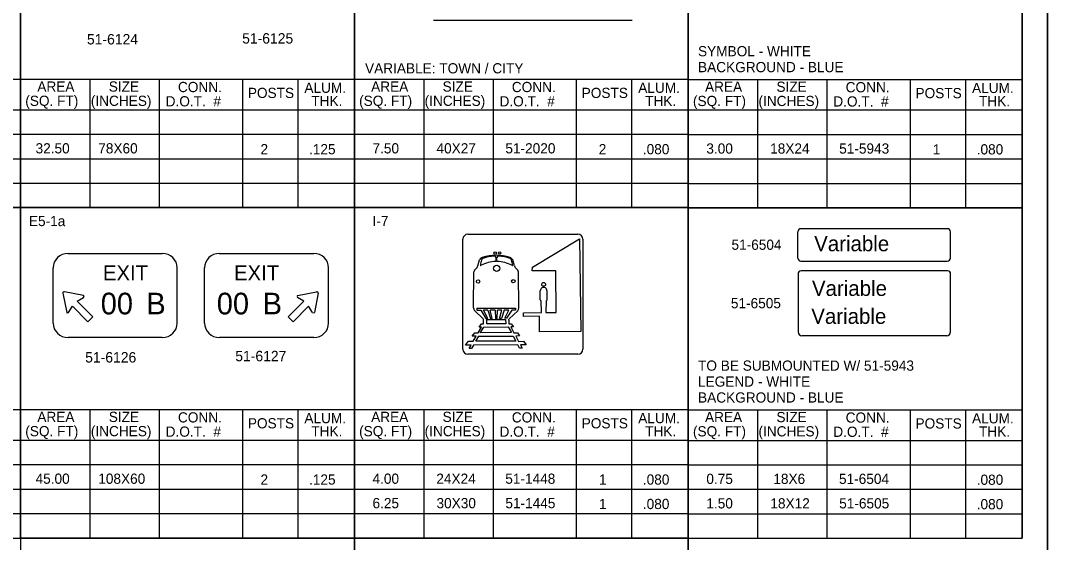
# Model space of a CAD drawing. Extents: x 0 to 2011, y -22 to 1183.
# Drawn here: x 947.8 to 1270, y 495.4 to 659.1 of the extents above; entities that cross this region are included whole.
import ezdxf

# ---------------------------------------------------------------- set-up
doc = ezdxf.new("R2010")
doc.units = 0
for name, color, linetype in [('CT_Border_Perimeter_Shape', 7, 'Continuous'), ('CT_Construction', 7, 'Continuous'), ('Level 1', 7, 'Continuous'), ('Level 2', 7, 'Continuous'), ('Level 5', 7, 'Continuous')]:
    doc.layers.add(name, color=color, linetype=linetype)

msp = doc.modelspace()

# ---------------------------------------------------------------- linework, layer by layer
at = {"layer": 'CT_Border_Perimeter_Shape'}
msp.add_lwpolyline([(0, -0.97), (1270, -0.97), (1270, 829.03), (0, 829.03)], close=True, dxfattribs=at)
at = {"layer": 'CT_Construction'}
msp.add_lwpolyline([(0, 829.03), (1270, 829.03), (1270, 59.03), (0, 59.03)], close=True, dxfattribs=at)
at = {"layer": 'Level 1'}
for p, q in [((1139.68, 659.13), (1077.32, 659.13)), ((1238.58, 593.82), (1192.65, 593.82)), ((1086.58, 556), (1086.58, 590.55)), ((1088.13, 592.1), (1122.68, 592.1)), ((1124.23, 590.55), (1124.23, 556)), ((1191.68, 584.63), (1191.68, 592.86)), ((1239.54, 584.63), (1239.54, 592.86)), ((962.59, 586.1), (992.27, 586.1)), ((1010.09, 586.1), (1039.77, 586.1)), ((1091.25, 582.22), (1091.84, 584.12)), ((1097.01, 583.77), (1097.02, 584.85)), ((1097.24, 583.77), (1097.23, 584.85)), ((1102.79, 582.19), (1102.2, 584.09)), ((1192.65, 583.67), (1238.58, 583.67)), ((958.02, 564.24), (958.02, 581.56)), ((996.94, 564.24), (996.94, 581.56)), ((1005.53, 564.24), (1005.53, 581.56)), ((1044.45, 564.24), (1044.45, 581.56)), ((1238.65, 580.59), (1192.72, 580.59)), ((1191.75, 579.62), (1191.75, 561.48)), ((1239.61, 561.48), (1239.61, 579.62)), ((961.05, 573.58), (962.26, 567.54)), ((967.57, 572.86), (961.54, 574.07)), ((1034.66, 572.86), (1040.69, 574.07)), ((1041.18, 573.58), (1039.98, 567.54)), ((965.54, 571.06), (967.57, 572.27)), ((970.5, 566.21), (965.54, 571.06)), ((1031.73, 566.21), (1036.7, 571.06)), ((1036.7, 571.06), (1034.66, 572.27)), ((962.85, 567.54), (964.06, 569.58)), ((964.06, 569.58), (968.9, 564.62)), ((1038.17, 569.58), (1033.33, 564.62)), ((1039.39, 567.54), (1038.17, 569.58)), ((1101.13, 565.56), (1103.78, 568.1)), ((968.9, 564.62), (970.5, 566.21)), ((1033.33, 564.62), (1031.73, 566.21)), ((1100.97, 565.12), (1101.01, 565.34)), ((1101.01, 565.34), (1101.13, 565.56)), ((992.27, 559.7), (962.69, 559.7)), ((1039.77, 559.7), (1010.2, 559.7)), ((1238.4, 560.27), (1192.96, 560.27)), ((1122.68, 554.45), (1088.13, 554.45)), ((1089.3, 556.23), (1088.5, 556.23))]:
    msp.add_line(p, q, dxfattribs=at)
for points in [[(1112.68, 571.19), (1112.57, 567.56), (1115.86, 567.56), (1115.79, 580.59), (1108.34, 580.58), (1108.37, 581.82), (1123.21, 590.65), (1123.57, 561.59)], [(1089.94, 568.98), (1090.05, 580.26)], [(1104.1, 568.95), (1103.99, 580.23)], [(1110.84, 571.52), (1110.85, 574.33)], [(1113, 571.48), (1112.99, 574.29)], [(1123.57, 561.59), (1110.63, 561.45), (1110.6, 566.39), (1105.57, 566.34), (1105.58, 567.49), (1111.29, 567.57), (1111.16, 571.24)], [(1088.5, 556.23), (1089.14, 557.31), (1087.38, 557.33), (1088.3, 558.52), (1089.85, 558.52), (1090.74, 560.13), (1089.54, 560.13), (1090.35, 561.21), (1091.42, 561.18), (1092.37, 562.95), (1091.67, 562.97), (1092.41, 564.01), (1092.89, 564), (1093.05, 564), (1093.07, 565.15), (1093.03, 565.37), (1092.91, 565.59), (1090.26, 568.13)], [(1090.98, 568.9), (1090.97, 568.27), (1092.2, 568.27)], [(1090.98, 568.9), (1103.14, 568.93), (1103.14, 568.32), (1101.91, 568.31)], [(1092.2, 568.27), (1093.82, 565.71), (1094.39, 565.71), (1093.08, 568.28)], [(1094.36, 568.28), (1093.08, 568.28)], [(1094.36, 568.28), (1095.2, 565.71), (1095.79, 565.71), (1095.09, 568.28)], [(1096.75, 568.29), (1095.09, 568.28)], [(1096.75, 568.29), (1096.81, 565.71), (1097.35, 565.71), (1097.43, 568.29)], [(1098.82, 568.3), (1097.43, 568.3)], [(1099.55, 568.3), (1098.7, 565.7), (1098.11, 565.7), (1098.82, 568.3)], [(1101.03, 568.31), (1099.55, 568.3)], [(1101.91, 568.31), (1100.28, 565.73), (1099.71, 565.73), (1101.03, 568.31)], [(1100.97, 565.12), (1100.98, 564.01), (1101.75, 564), (1102.41, 563.01), (1101.59, 563.01), (1102.55, 561.19), (1103.69, 561.2), (1104.38, 560.19), (1103.17, 560.13), (1104.04, 558.49), (1105.59, 558.51), (1106.39, 557.39), (1104.66, 557.39), (1105.21, 556.34), (1104.38, 556.35), (1103.83, 557.36), (1089.91, 557.33), (1089.3, 556.23)], [(1094.11, 565.31), (1099.99, 565.34), (1100.02, 564.02), (1094.1, 563.99), (1094.11, 565.31)], [(1093.07, 562.95), (1100.77, 563.02), (1101.83, 561.23), (1092.05, 561.18), (1093.14, 562.93)], [(1091.49, 560.11), (1102.35, 560.15), (1103.2, 558.54), (1090.61, 558.53), (1091.56, 560.09)]]:
    msp.add_lwpolyline(points, dxfattribs=at)
for centre, radius in [((1096.69, 586.21), 0.407), ((1098.13, 586.22), 0.407), ((1097.19, 581.41), 1), ((1091.36, 577.28), 0.535), ((1102.4, 577.34), 0.535), ((1111.9, 576.36), 0.598)]:
    msp.add_circle(centre, radius, dxfattribs=at)
for centre, radius, start, end in [((1192.65, 592.86), 0.968, 90, 180), ((1238.58, 592.86), 0.968, 360, 90), ((1088.13, 590.55), 1.55, 90, 180), ((1122.68, 590.55), 1.55, 0, 90), ((1092.99, 583.55), 1.28, 104.4029, 153.5069), ((1099.22, 581.59), 7.21, 160.8398, 173.2704), ((1097.46, 572.25), 11.36, 92.9416, 117.1252), ((1093.01, 583.89), 0.6, 103.6949, 173.6857), ((1096.98, 571.86), 13.63, 71.1878, 108.433), ((1096.67, 574.66), 10.53, 90.8903, 111.1999), ((1096.54, 584.68), 0.506, 19.0492, 93.9205), ((1096.84, 583.76), 0.173, 283.9226, 2.456), ((1097.71, 584.68), 0.506, 86.0795, 160.9508), ((1097.41, 583.76), 0.173, 177.544, 256.0774), ((1096.79, 572.25), 11.36, 62.8748, 87.0584), ((1097.58, 574.66), 10.53, 68.8001, 89.1097), ((1101.06, 583.52), 1.28, 26.4931, 75.5971), ((1101.25, 583.89), 0.6, 6.3143, 76.3051), ((1095.04, 581.59), 7.21, 6.7296, 19.1602), ((1192.65, 584.63), 0.968, 180, 270), ((1238.58, 584.63), 0.968, 270, 0), ((1091.47, 580.13), 1.43, 126.0727, 174.8195), ((1089.52, 582.7), 1.8, 308.031, 344.3003), ((1092.19, 582.45), 0.128, 182.8654, 318.1939), ((1102.07, 582.45), 0.128, 221.806, 357.1346), ((1104.52, 582.67), 1.8, 195.6997, 231.969), ((1102.58, 580.11), 1.43, 5.1805, 53.9273), ((1192.72, 579.62), 0.968, 90, 180), ((1238.64, 579.62), 0.968, 360, 90), ((961.46, 573.66), 0.418, 78.7145, 191.291), ((1040.77, 573.66), 0.418, 348.709, 101.2855), ((1111.92, 574.33), 1.07, 357.9657, 179.6228), ((967.28, 572.57), 0.418, 315, 45), ((1034.95, 572.57), 0.418, 135, 225), ((1111.19, 571.6), 0.362, 191.7388, 264.7446), ((1112.65, 571.55), 0.362, 275.2554, 348.2612), ((962.55, 567.84), 0.418, 225, 315), ((1039.68, 567.84), 0.418, 225, 315), ((1091.23, 568.97), 1.28, 179.499, 221.231), ((1102.82, 568.94), 1.28, 318.769, 0.501), ((1192.96, 561.48), 1.21, 180, 270), ((1238.4, 561.48), 1.21, 270, 360), ((1088.13, 556), 1.55, 180, 270), ((1122.68, 556), 1.55, 270, 0)]:
    msp.add_arc(centre, radius, start, end, dxfattribs=at)
for centre, major_axis, ratio, start_param, end_param in [((962.69, 581.56), (-4.67, 0), 0.970874, 4.712389, 6.283185), ((992.27, 581.56), (-4.67, 0), 0.97089, 3.141593, 4.712389), ((1010.2, 581.56), (-4.67, 0), 0.970874, 4.712389, 6.283185), ((1039.77, 581.56), (-4.67, 0), 0.97089, 3.141593, 4.712389), ((962.69, 564.24), (4.67, 0), 0.970874, 3.141593, 4.712389), ((992.27, 564.24), (4.67, 0), 0.970874, 4.712389, 6.283185), ((1010.2, 564.24), (4.67, 0), 0.970874, 3.141593, 4.712389), ((1039.77, 564.24), (4.67, 0), 0.970874, 4.712389, 6.283185)]:
    msp.add_ellipse(centre, major_axis=major_axis, ratio=ratio, start_param=start_param, end_param=end_param, dxfattribs=at)
at = {"layer": 'Level 2'}
for p, q in [((843.04, 640.71), (947.79, 640.71)), ((947.79, 640.71), (1052.53, 640.71)), ((969.54, 640.71), (969.54, 600.44)), ((991.29, 640.71), (991.29, 600.44)), ((1017.39, 640.71), (1017.39, 600.44)), ((1034.79, 640.71), (1034.79, 600.44)), ((1052.53, 640.71), (1157.28, 640.71)), ((1074.28, 640.71), (1074.28, 600.44)), ((1096.03, 640.71), (1096.03, 600.44)), ((1122.13, 640.71), (1122.13, 600.44)), ((1139.53, 640.71), (1139.53, 600.44)), ((1157.28, 640.66), (1262.03, 640.66)), ((1179.03, 640.66), (1179.03, 600.38)), ((1200.78, 640.66), (1200.78, 600.38)), ((1226.88, 640.66), (1226.88, 600.38)), ((1244.28, 640.66), (1244.28, 600.38)), ((843.04, 631.12), (947.79, 631.12)), ((947.79, 631.12), (1052.53, 631.12)), ((1052.53, 631.12), (1157.28, 631.12)), ((1157.28, 631.07), (1262.03, 631.07)), ((843.04, 623.45), (947.79, 623.45)), ((947.79, 623.45), (1052.53, 623.45)), ((1052.53, 623.45), (1157.28, 623.45)), ((1157.28, 623.4), (1262.03, 623.4)), ((843.04, 615.78), (947.79, 615.78)), ((947.79, 615.78), (1052.53, 615.78)), ((1052.53, 615.78), (1157.28, 615.78)), ((1157.28, 615.72), (1262.03, 615.72)), ((843.04, 608.11), (947.79, 608.11)), ((947.79, 608.11), (1052.53, 608.11)), ((1052.53, 608.11), (1157.28, 608.11)), ((1157.28, 608.05), (1262.03, 608.05)), ((843.04, 537.09), (947.79, 537.09)), ((947.79, 537.09), (1052.53, 537.09)), ((969.54, 537.09), (969.54, 496.81)), ((991.29, 537.09), (991.29, 496.81)), ((1017.39, 537.09), (1017.39, 496.81)), ((1034.79, 537.09), (1034.79, 496.81)), ((1052.53, 537.09), (1157.28, 537.09)), ((1074.28, 537.09), (1074.28, 496.81)), ((1096.03, 537.09), (1096.03, 496.81)), ((1122.13, 537.09), (1122.13, 496.81)), ((1139.53, 537.09), (1139.53, 496.81)), ((1157.28, 537.03), (1262.03, 537.03)), ((1179.03, 537.03), (1179.03, 496.76)), ((1200.78, 537.03), (1200.78, 496.76)), ((1226.88, 537.03), (1226.88, 496.76)), ((1244.28, 537.03), (1244.28, 496.76)), ((843.04, 527.5), (947.79, 527.5)), ((947.79, 527.5), (1052.53, 527.5)), ((1052.53, 527.5), (1157.28, 527.5)), ((1157.28, 527.44), (1262.03, 527.44)), ((843.04, 519.83), (947.79, 519.83)), ((947.79, 519.83), (1052.53, 519.83)), ((1052.53, 519.83), (1157.28, 519.83)), ((1157.28, 519.77), (1262.03, 519.77)), ((843.04, 512.16), (947.79, 512.16)), ((947.79, 512.16), (1052.53, 512.16)), ((1052.53, 512.16), (1157.28, 512.16)), ((1157.28, 512.1), (1262.03, 512.1)), ((843.04, 504.48), (947.79, 504.48)), ((947.79, 504.48), (1052.53, 504.48)), ((1052.53, 504.48), (1157.28, 504.48)), ((1157.28, 504.43), (1262.03, 504.43))]:
    msp.add_line(p, q, dxfattribs=at)
for points in [[(947.79, 704.06), (843.04, 704.06), (843.04, 600.44), (947.79, 600.44)], [(1052.53, 704.06), (947.79, 704.06), (947.79, 600.44), (1052.53, 600.44)], [(1157.28, 704.06), (1052.53, 704.06), (1052.53, 600.44), (1157.28, 600.44)], [(1262.03, 704), (1157.28, 704), (1157.28, 600.38), (1262.03, 600.38)], [(947.79, 600.44), (843.04, 600.44), (843.04, 496.81), (947.79, 496.81)], [(1052.53, 600.44), (947.79, 600.44), (947.79, 496.81), (1052.53, 496.81)], [(1157.28, 600.44), (1052.53, 600.44), (1052.53, 496.81), (1157.28, 496.81)], [(1262.03, 600.38), (1157.28, 600.38), (1157.28, 496.76), (1262.03, 496.76)], [(1052.53, 496.81), (947.79, 496.81), (947.79, 393.19), (1052.53, 393.19)], [(1157.28, 496.81), (1052.53, 496.81), (1052.53, 393.19), (1157.28, 393.19)]]:
    msp.add_lwpolyline(points, close=True, dxfattribs=at)
at = {"layer": 'Level 5'}
for p, q in [((947.79, 830), (947.79, 496.81)), ((1052.53, 830), (1052.53, 393.19)), ((1157.28, 830), (1157.28, 393.19)), ((1262.03, 830), (1262.03, 496.76)), ((1157.28, 722.51), (1157.28, 496.61))]:
    msp.add_line(p, q, dxfattribs=at)

# ---------------------------------------------------------------- texts
at = {"layer": 'Level 1'}
for s, p in [('51-6124', (968.63, 651.63)), ('51-6125', (1017.32, 651.9)), ('51-6126', (968.08, 551.86)), ('51-6127', (1015.17, 552.26))]:
    msp.add_text(s, height=3.264, dxfattribs=at).set_placement(p)
at = {"layer": 'Level 2'}
for s, height, p in [('SYMBOL - WHITE', 3.2, (1160.36, 647.92)), ('VARIABLE: TOWN / CITY', 3.2, (1055.88, 642.55)), ('BACKGROUND - BLUE', 3.2, (1160.36, 642.92)), ('AREA', 3.2, (953.05, 636.83)), ('SIZE', 3.2, (975.47, 636.83)), ('CONN.', 3.2, (997.18, 636.68)), ('POSTS', 3.2, (1019.11, 634.83)), ('ALUM.', 3.2, (1036.85, 636.45)), ('AREA', 3.2, (1057.8, 636.83)), ('SIZE', 3.2, (1080.21, 636.83)), ('CONN.', 3.2, (1101.93, 636.68)), ('POSTS', 3.2, (1123.86, 634.83)), ('ALUM.', 3.2, (1141.6, 636.45)), ('AREA', 3.2, (1162.55, 636.77)), ('SIZE', 3.2, (1184.96, 636.77)), ('CONN.', 3.2, (1206.68, 636.62)), ('POSTS', 3.2, (1228.6, 634.77)), ('ALUM.', 3.2, (1246.34, 636.39)), ('(SQ. FT)', 3.2, (949.27, 632.36)), ('(INCHES)', 3.2, (969.84, 632.36)), ('D.O.T.  #', 3.2, (993.32, 632.2)), ('THK.', 3.2, (1039.03, 632.31)), ('(SQ. FT)', 3.2, (1054.02, 632.36)), ('(INCHES)', 3.2, (1074.58, 632.36)), ('D.O.T.  #', 3.2, (1098.07, 632.2)), ('THK.', 3.2, (1143.77, 632.31)), ('(SQ. FT)', 3.2, (1158.77, 632.3)), ('(INCHES)', 3.2, (1179.33, 632.3)), ('D.O.T.  #', 3.2, (1202.81, 632.15)), ('THK.', 3.2, (1248.52, 632.25)), ('E5-1a', 3.2, (950.42, 594.64)), ('I-7', 3.2, (1058.24, 594.64)), ('51-6504', 3.2, (1170.86, 587.21)), ('Variable', 4.8, (1196.8, 586.76)), ('EXIT', 4.763, (973.64, 577.6)), ('EXIT', 4.763, (1014.76, 577.6)), ('Variable', 4.8, (1196.1, 572.74)), ('00', 6.804, (972.95, 566.95)), ('B', 6.8, (987.27, 566.95)), ('00', 6.804, (1009.36, 566.95)), ('B', 6.8, (1023.77, 566.95)), ('51-6505', 3.2, (1170.67, 568.88)), ('Variable', 4.8, (1195.89, 563.99)), ('TO BE SUBMOUNTED W/ 51-5943', 3.2, (1160.36, 549.29)), ('LEGEND - WHITE', 3.2, (1160.36, 544.29)), ('BACKGROUND - BLUE', 3.2, (1160.36, 539.29)), ('AREA', 3.2, (953.05, 533.21)), ('SIZE', 3.2, (975.47, 533.21)), ('CONN.', 3.2, (997.18, 533.05)), ('ALUM.', 3.2, (1036.85, 532.83)), ('AREA', 3.2, (1057.8, 533.21)), ('SIZE', 3.2, (1080.21, 533.21)), ('CONN.', 3.2, (1101.93, 533.05)), ('ALUM.', 3.2, (1141.6, 532.83)), ('AREA', 3.2, (1162.55, 533.15)), ('SIZE', 3.2, (1184.96, 533.15)), ('CONN.', 3.2, (1206.68, 533)), ('ALUM.', 3.2, (1246.34, 532.77)), ('(SQ. FT)', 3.2, (949.27, 528.74)), ('(INCHES)', 3.2, (969.84, 528.74)), ('D.O.T.  #', 3.2, (993.32, 528.58)), ('POSTS', 3.2, (1019.11, 531.2)), ('THK.', 3.2, (1039.03, 528.69)), ('(SQ. FT)', 3.2, (1054.02, 528.74)), ('(INCHES)', 3.2, (1074.58, 528.74)), ('D.O.T.  #', 3.2, (1098.07, 528.58)), ('POSTS', 3.2, (1123.86, 531.2)), ('THK.', 3.2, (1143.77, 528.69)), ('(SQ. FT)', 3.2, (1158.77, 528.68)), ('(INCHES)', 3.2, (1179.33, 528.68)), ('D.O.T.  #', 3.2, (1202.81, 528.53)), ('POSTS', 3.2, (1228.6, 531.15)), ('THK.', 3.2, (1248.52, 528.63))]:
    msp.add_text(s, height=height, dxfattribs=at).set_placement(p)
at = {"layer": 'Level 5'}
for s, p in [('32.50', (952.5, 617.45)), ('78X60 ', (972.17, 617.45)), ('2 ', (1023.08, 617.18)), ('.125', (1038.31, 617.18)), (' 7.50', (1057.03, 617.45)), ('40X27', (1078.3, 617.45)), ('51-2020', (1099.91, 617.45)), ('2', (1129.21, 617.18)), ('.080', (1143.05, 617.18)), (' 3.00', (1161.78, 617.39)), ('18X24', (1182.99, 617.39)), ('51-5943', (1204.65, 617.39)), ('1', (1234.02, 617.13)), ('.080', (1247.8, 617.13)), ('45.00', (952.5, 513.82)), ('108X60', (972.17, 513.82)), ('2 ', (1023.08, 513.56)), ('.125', (1038.31, 513.56)), (' 4.00', (1057.03, 513.82)), ('24X24', (1078.24, 513.82)), ('51-1448', (1099.88, 513.82)), ('1', (1129.27, 513.56)), ('.080', (1143.05, 513.56)), (' 0.75', (1161.78, 513.77)), (' 18X6', (1182.8, 513.77)), ('51-6504', (1204.59, 513.77)), ('.080', (1247.8, 513.5)), (' 6.25', (1057.03, 506.15)), ('30X30', (1078.3, 506.15)), ('51-1445', (1099.91, 506.15)), ('.080', (1143.05, 505.89)), (' 1.50', (1161.78, 506.09)), ('18X12', (1183.05, 506.09)), ('51-6505', (1204.65, 506.09)), ('1', (1129.27, 505.89)), ('.080', (1247.8, 505.83))]:
    msp.add_text(s, height=3.2, dxfattribs=at).set_placement(p)

doc.saveas('drawing.dxf')
